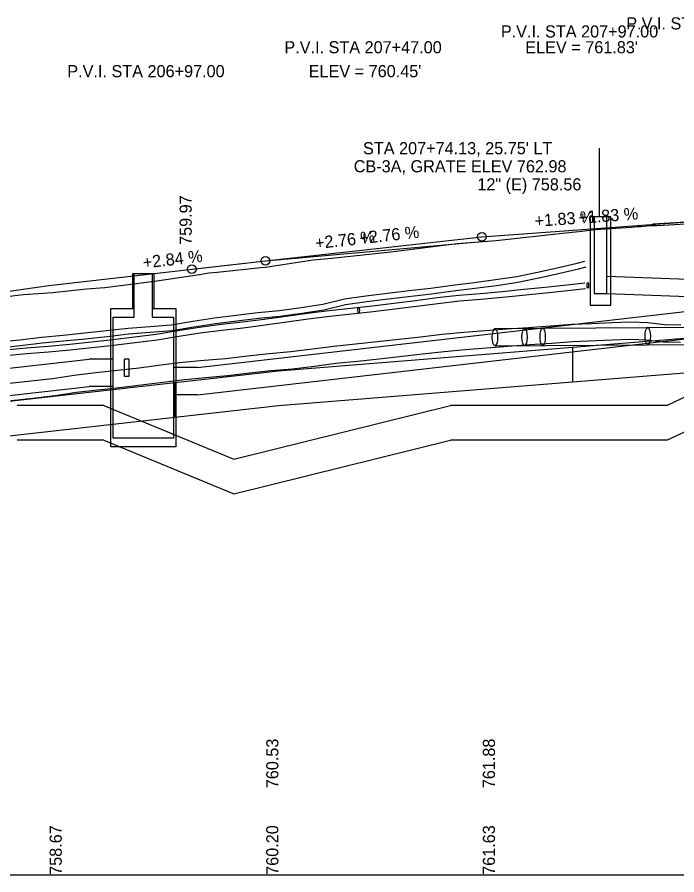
# Model space of a CAD drawing. Extents: x 1833473 to 1837132, y 704683 to 706683.
# Drawn here: x 1834350.5 to 1834502.8, y 705682.6 to 705880.7 of the extents above; entities that cross this region are included whole.
import ezdxf

# ---------------------------------------------------------------- set-up
doc = ezdxf.new("R2010")
doc.units = 0
for name, color, linetype in [('DR_P_Storm_Sewer', 7, 'Continuous'), ('DR_P_Text', 7, 'Continuous'), ('GK_Cells', 7, 'Continuous'), ('PF_P_Grade_Line', 7, 'Continuous'), ('PF_P_Text', 7, 'Continuous'), ('PF_X_Ground_Line', 7, 'Continuous'), ('PF_X_Text', 7, 'Continuous'), ('UT_P_Electric', 7, 'Continuous'), ('UT_P_Telecom', 7, 'Continuous'), ('UT_P_Water', 7, 'Continuous'), ('UT_X_Electric', 7, 'Continuous'), ('UT_X_Water', 7, 'Continuous')]:
    doc.layers.add(name, color=color, linetype=linetype)

msp = doc.modelspace()

# ---------------------------------------------------------------- linework, layer by layer
at = {"layer": 'DR_P_Storm_Sewer'}
for p, q in [((1834484.91, 705834.57), (1834484.91, 705834.57)), ((1834486.63, 705820.89), (1834572.5, 705817.65)), ((1834486.63, 705816.89), (1834572.5, 705813.65))]:
    msp.add_line(p, q, dxfattribs=at)
for points in [[(1834482.79, 705834.57), (1834482.79, 705814.22), (1834487.54, 705814.22), (1834487.54, 705834.57), (1834482.79, 705834.57)], [(1834483.69, 705834.57), (1834483.69, 705816.89), (1834486.63, 705816.89), (1834486.63, 705834.57)]]:
    msp.add_lwpolyline(points, dxfattribs=at)
at = {"layer": 'DR_P_Text'}
msp.add_line((1834484.84, 705850.45), (1834484.84, 705842.11), dxfattribs=at)
msp.add_lwpolyline([(1834484.91, 705834.57), (1834484.91, 705846.28), (1834484.84, 705846.28)], dxfattribs=at)
at = {"layer": 'GK_Cells'}
msp.add_line((1833710.78, 705682.65), (1834910.78, 705682.65), dxfattribs=at)
msp.add_line((1833710.78, 705682.65), (1834910.78, 705682.65), dxfattribs=at)
at = {"layer": 'PF_P_Grade_Line'}
for p, q in [((1834457.78, 705829.97), (1834507.78, 705833.62)), ((1834407.78, 705824.45), (1834457.78, 705829.97)), ((1834407.78, 705824.45), (1834457.78, 705828.93)), ((1834357.78, 705818.77), (1834407.78, 705824.45)), ((1834390.78, 705822.52), (1834407.78, 705824.45)), ((1834307.78, 705811.69), (1834357.78, 705818.77))]:
    msp.add_line(p, q, dxfattribs=at)
at = {"layer": 'PF_P_Text'}
msp.add_line((1834497.26, 705832.95), (1834535.78, 705835.41), dxfattribs=at)
for centre in [(1834457.78, 705829.97), (1834407.78, 705824.45), (1834390.78, 705822.52)]:
    msp.add_circle(centre, 1, dxfattribs=at)
at = {"layer": 'PF_X_Ground_Line'}
msp.add_lwpolyline([(1834346.68, 705816.02), (1834351.98, 705816.68), (1834358.7, 705817.1), (1834366.53, 705817.94), (1834370.72, 705818.32), (1834374.31, 705818.75), (1834382.73, 705819.8), (1834392.55, 705821.32), (1834394.75, 705821.65), (1834396.63, 705821.82), (1834406.76, 705822.89), (1834407.8, 705823.01), (1834418.78, 705824.64), (1834421.37, 705824.88), (1834423.15, 705825.04), (1834435.27, 705826.37), (1834436.74, 705826.53), (1834452.05, 705828.47), (1834461.08, 705829.17), (1834476.34, 705830.82), (1834480.14, 705831.24), (1834484.02, 705831.66), (1834492.19, 705832.25), (1834492.97, 705832.3), (1834493.73, 705832.34), (1834494.55, 705832.37), (1834495.85, 705832.49), (1834496.9, 705832.59), (1834497.68, 705832.6), (1834498.28, 705832.64), (1834510.01, 705833.28)], dxfattribs=at)
at = {"layer": 'UT_P_Electric'}
for p, q in [((1834377.16, 705813.47), (1834377.16, 705821.5)), ((1834377.16, 705821.5), (1834382.08, 705821.5)), ((1834377.49, 705811.47), (1834377.49, 705821.5)), ((1834381.74, 705811.47), (1834381.74, 705821.5)), ((1834382.08, 705813.47), (1834382.08, 705821.5)), ((1834392.11, 705799.79), (1834540.6, 705816.88)), ((1834372.13, 705781.47), (1834372.13, 705813.47)), ((1834372.13, 705813.47), (1834377.49, 705813.47)), ((1834381.74, 705813.47), (1834387.11, 705813.47)), ((1834387.11, 705813.47), (1834387.11, 705781.47)), ((1834372.63, 705783.47), (1834372.63, 705811.47)), ((1834372.63, 705811.47), (1834377.49, 705811.47)), ((1834381.74, 705811.47), (1834386.61, 705811.47)), ((1834386.61, 705811.47), (1834386.61, 705783.47)), ((1834392.11, 705793.46), (1834540.64, 705810.55)), ((1834165.01, 705779.12), (1834367.13, 705801.76)), ((1834372.63, 705801.76), (1834367.13, 705801.76)), ((1834376.29, 705801.76), (1834375.28, 705801.76)), ((1834375.28, 705797.76), (1834375.28, 705801.76)), ((1834376.29, 705801.76), (1834376.29, 705797.76)), ((1834392.11, 705799.79), (1834386.61, 705799.79)), ((1834376.29, 705797.76), (1834375.28, 705797.76)), ((1834165.01, 705772.79), (1834367.13, 705795.43)), ((1834372.63, 705795.43), (1834367.13, 705795.43)), ((1834392.11, 705793.46), (1834386.61, 705793.46)), ((1834386.61, 705783.47), (1834372.63, 705783.47)), ((1834387.11, 705781.47), (1834372.13, 705781.47))]:
    msp.add_line(p, q, dxfattribs=at)
at = {"layer": 'UT_P_Telecom'}
for p, q in [((1834410.78, 705799.07), (1834535.78, 705809.12)), ((1834478.65, 705804.53), (1834478.65, 705796.53)), ((1834410.78, 705791.07), (1834535.78, 705801.12)), ((1834175.78, 705772.5), (1834410.78, 705799.07)), ((1834386.91, 705796.37), (1834386.91, 705788.37)), ((1834175.78, 705764.5), (1834410.78, 705791.07))]:
    msp.add_line(p, q, dxfattribs=at)
at = {"layer": 'UT_P_Water'}
for p, q in [((1834460.78, 705808.8), (1834550.3, 705809.43)), ((1834460.8, 705804.8), (1834550.3, 705805.43))]:
    msp.add_line(p, q, dxfattribs=at)
for centre in [(1834460.78, 705806.8), (1834467.61, 705806.85), (1834471.79, 705806.87), (1834496.04, 705807.05)]:
    msp.add_ellipse(centre, major_axis=(0, -2), ratio=0.304231, dxfattribs=at)
at = {"layer": 'UT_X_Electric'}
for p, q in [((1834500.49, 705791.07), (1834540.49, 705809.98)), ((1834500.49, 705783.06), (1834540.49, 705801.96)), ((1834370.49, 705791.07), (1834350.49, 705791.07)), ((1834370.49, 705791.07), (1834400.49, 705778.66)), ((1834400.49, 705778.66), (1834450.49, 705791.07)), ((1834500.49, 705791.07), (1834450.49, 705791.07)), ((1834370.49, 705783.06), (1834350.49, 705783.06)), ((1834370.49, 705783.06), (1834400.49, 705770.65)), ((1834400.49, 705770.65), (1834450.49, 705783.06)), ((1834500.49, 705783.06), (1834450.49, 705783.06))]:
    msp.add_line(p, q, dxfattribs=at)
for points in [[(1834455.97, 705819.46), (1834460.94, 705820.1), (1834465.86, 705820.85), (1834470.61, 705821.79), (1834475.17, 705822.84), (1834479.74, 705823.93), (1834481.53, 705824.36)], [(1834456.15, 705818.14), (1834461.13, 705818.78), (1834466.09, 705819.53), (1834470.89, 705820.48), (1834475.48, 705821.54), (1834480.05, 705822.63), (1834481.84, 705823.07)], [(1834346.1, 705805.71), (1834351.1, 705806.22), (1834356.1, 705806.81), (1834361.09, 705807.29), (1834366.09, 705807.79), (1834371.08, 705808.32), (1834376.08, 705808.88), (1834381.08, 705809.28), (1834386.07, 705809.7), (1834391.07, 705810.54), (1834396.06, 705811.26), (1834401.06, 705811.91), (1834406.05, 705812.52), (1834411.04, 705812.96), (1834416.03, 705813.65), (1834421.02, 705814.47), (1834426.02, 705815.64), (1834431.01, 705816.36), (1834436, 705816.97), (1834440.99, 705817.56), (1834445.98, 705818.16), (1834450.98, 705818.83), (1834455.97, 705819.46)], [(1834347.64, 705803.91), (1834352.63, 705804.33), (1834357.63, 705804.73), (1834362.62, 705805.21), (1834367.61, 705805.74), (1834372.6, 705806.3), (1834377.59, 705806.9), (1834382.58, 705807.54), (1834387.57, 705808.37), (1834392.56, 705809.15), (1834397.55, 705809.78), (1834402.54, 705810.33), (1834407.53, 705810.95), (1834412.52, 705811.66), (1834417.51, 705812.39), (1834422.5, 705813), (1834427.49, 705813.53), (1834432.48, 705814.08), (1834437.47, 705814.69), (1834442.46, 705815.32), (1834447.45, 705815.94), (1834452.44, 705816.54), (1834457.43, 705816.92), (1834462.42, 705817.35), (1834467.41, 705817.87), (1834472.4, 705818.38), (1834477.39, 705818.93), (1834481.53, 705819.4)], [(1834346.23, 705804.38), (1834351.25, 705804.89), (1834356.24, 705805.48), (1834361.22, 705805.97), (1834366.23, 705806.46), (1834371.23, 705807), (1834376.21, 705807.55), (1834381.18, 705807.95), (1834386.24, 705808.38), (1834391.27, 705809.22), (1834396.24, 705809.94), (1834401.22, 705810.58), (1834406.19, 705811.19), (1834411.19, 705811.64), (1834416.23, 705812.33), (1834421.28, 705813.16), (1834426.26, 705814.33), (1834431.18, 705815.03), (1834436.16, 705815.64), (1834446.15, 705816.83), (1834451.15, 705817.51), (1834456.14, 705818.14)], [(1834347.78, 705802.59), (1834352.74, 705803.01), (1834357.74, 705803.4), (1834362.75, 705803.88), (1834367.75, 705804.41), (1834372.75, 705804.98), (1834377.75, 705805.58), (1834382.77, 705806.22), (1834387.78, 705807.05), (1834392.75, 705807.83), (1834397.71, 705808.46), (1834402.69, 705809), (1834407.71, 705809.63), (1834412.71, 705810.34), (1834417.69, 705811.07), (1834422.65, 705811.67), (1834427.63, 705812.21), (1834432.63, 705812.75), (1834437.63, 705813.37), (1834447.61, 705814.62), (1834452.57, 705815.22), (1834457.53, 705815.59), (1834462.54, 705816.02), (1834472.54, 705817.05), (1834477.54, 705817.61), (1834481.68, 705818.07)]]:
    msp.add_lwpolyline(points, dxfattribs=at)
for centre in [(1834482.22, 705818.8), (1834429.32, 705813.05)]:
    msp.add_ellipse(centre, major_axis=(0, -0.667), ratio=0.250004, dxfattribs=at)
at = {"layer": 'UT_X_Water'}
for points in [[(1834348.7, 705796.17), (1834353.69, 705796.74), (1834358.68, 705797.28), (1834363.68, 705798.05), (1834368.67, 705798.63), (1834373.67, 705799.17), (1834378.66, 705799.75), (1834383.66, 705800.39), (1834388.65, 705801.04), (1834393.65, 705801.47), (1834398.64, 705801.92), (1834403.64, 705802.54), (1834408.63, 705803.07), (1834413.63, 705803.52), (1834418.63, 705804.11), (1834423.62, 705804.75), (1834428.61, 705805.25), (1834433.6, 705805.79), (1834438.59, 705806.35), (1834443.59, 705806.92), (1834448.59, 705807.48), (1834453.59, 705807.99), (1834458.57, 705808.35), (1834463.55, 705808.72), (1834468.54, 705809.08), (1834473.52, 705809.42), (1834478.5, 705809.8), (1834483.13, 705810.01), (1834487.76, 705810.23), (1834492.14, 705810.35), (1834496.04, 705810.22), (1834499.89, 705809.74), (1834503.71, 705809.63)], [(1834349.13, 705792.2), (1834354.13, 705792.76), (1834359.21, 705793.31), (1834364.22, 705794.09), (1834369.12, 705794.65), (1834374.11, 705795.19), (1834379.15, 705795.78), (1834389.08, 705797.06), (1834394, 705797.48), (1834399.07, 705797.94), (1834404.1, 705798.57), (1834409.03, 705799.09), (1834414.04, 705799.54), (1834419.11, 705800.14), (1834424.07, 705800.78), (1834429.03, 705801.27), (1834434.04, 705801.82), (1834444.04, 705802.94), (1834449.02, 705803.5), (1834453.94, 705804), (1834463.84, 705804.73), (1834468.82, 705805.09), (1834473.81, 705805.43), (1834478.74, 705805.81), (1834487.91, 705806.23), (1834492.13, 705806.34), (1834495.73, 705806.23), (1834499.59, 705805.75), (1834503.61, 705805.63)]]:
    msp.add_lwpolyline(points, dxfattribs=at)

# ---------------------------------------------------------------- texts
at = {"layer": 'DR_P_Text'}
for s, p in [("STA 207+74.13, 25.75' LT", (1834430.32, 705849.05)), ('CB-3A, GRATE ELEV 762.98', (1834428.18, 705844.88)), ('12" (E) 758.56', (1834456.71, 705840.71))]:
    msp.add_text(s, height=2.8, dxfattribs=at).set_placement(p)
at = {"layer": 'PF_P_Text'}
for s, p in [('P.V.I. STA 208+26.00', (1834491.1, 705877.87)), ('P.V.I. STA 207+97.00', (1834462.14, 705876.02)), ('P.V.I. STA 207+47.00', (1834412.17, 705872.37)), ("ELEV = 761.83'", (1834467.78, 705872.37)), ('P.V.I. STA 206+97.00', (1834362.06, 705866.85)), ("ELEV = 760.45'", (1834417.78, 705866.85))]:
    msp.add_text(s, height=2.8, dxfattribs=at).set_placement(p)
for s, rotation, p in [('759.97', 90, (1834390.78, 705828.12)), ('+1.83 %', 4.1752, (1834480.12, 705833)), ('+1.83 %', 4.1752, (1834470.02, 705832.27)), ('+2.76 %', 6.2999, (1834429.66, 705828.27)), ('+2.76 %', 6.2999, (1834419.42, 705827.14)), ('+2.84 %', 6.481, (1834379.65, 705822.66)), ('760.53', 90, (1834410.78, 705702.65)), ('761.88', 90, (1834460.78, 705702.65))]:
    msp.add_text(s, height=2.8, rotation=rotation, dxfattribs=at).set_placement(p)
at = {"layer": 'PF_X_Text'}
for s, p in [('758.67', (1834360.78, 705682.65)), ('760.20', (1834410.78, 705682.65)), ('761.63', (1834460.78, 705682.65))]:
    msp.add_text(s, height=2.8, rotation=90, dxfattribs=at).set_placement(p)

doc.saveas('drawing.dxf')
